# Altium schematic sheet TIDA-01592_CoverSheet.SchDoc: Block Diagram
size 431 x 279 mm; Date: Not shown in title block; ApprovedBy: Not shown in title block; CheckedBy: Not shown in title block; Author: Not shown in title block; CompanyName: Not shown in title block; DrawnBy: Abhishek Vishwa; Engineer: Abhishek Vishwa; Organization: Not shown in title block; Address1: Not shown in title block; Address2: Not shown in title block; Address3: Not shown in title block; Address4: Not shown in title block; DocumentNumber: 1; Revision: Use project parameter SCH_Rev; SheetNumber: 1; SheetTotal: 5; PageSetup: Record=PageOptions¦CenterHorizontal=True¦CenterVertical=True¦PrintScale=1.00¦XCorrection=1.00¦YCorrection=1.00¦PrintKind=0¦BorderSize=5000000¦LeftOffset=0¦BottomOffset=0¦Orientation=2¦PaperLength=1000¦PaperWidth=1000¦Scale=100¦PaperSource=15¦PrintQuality=600¦MediaType=1¦DitherType=10¦PaperKind=Letter¦PrintScaleMode=1
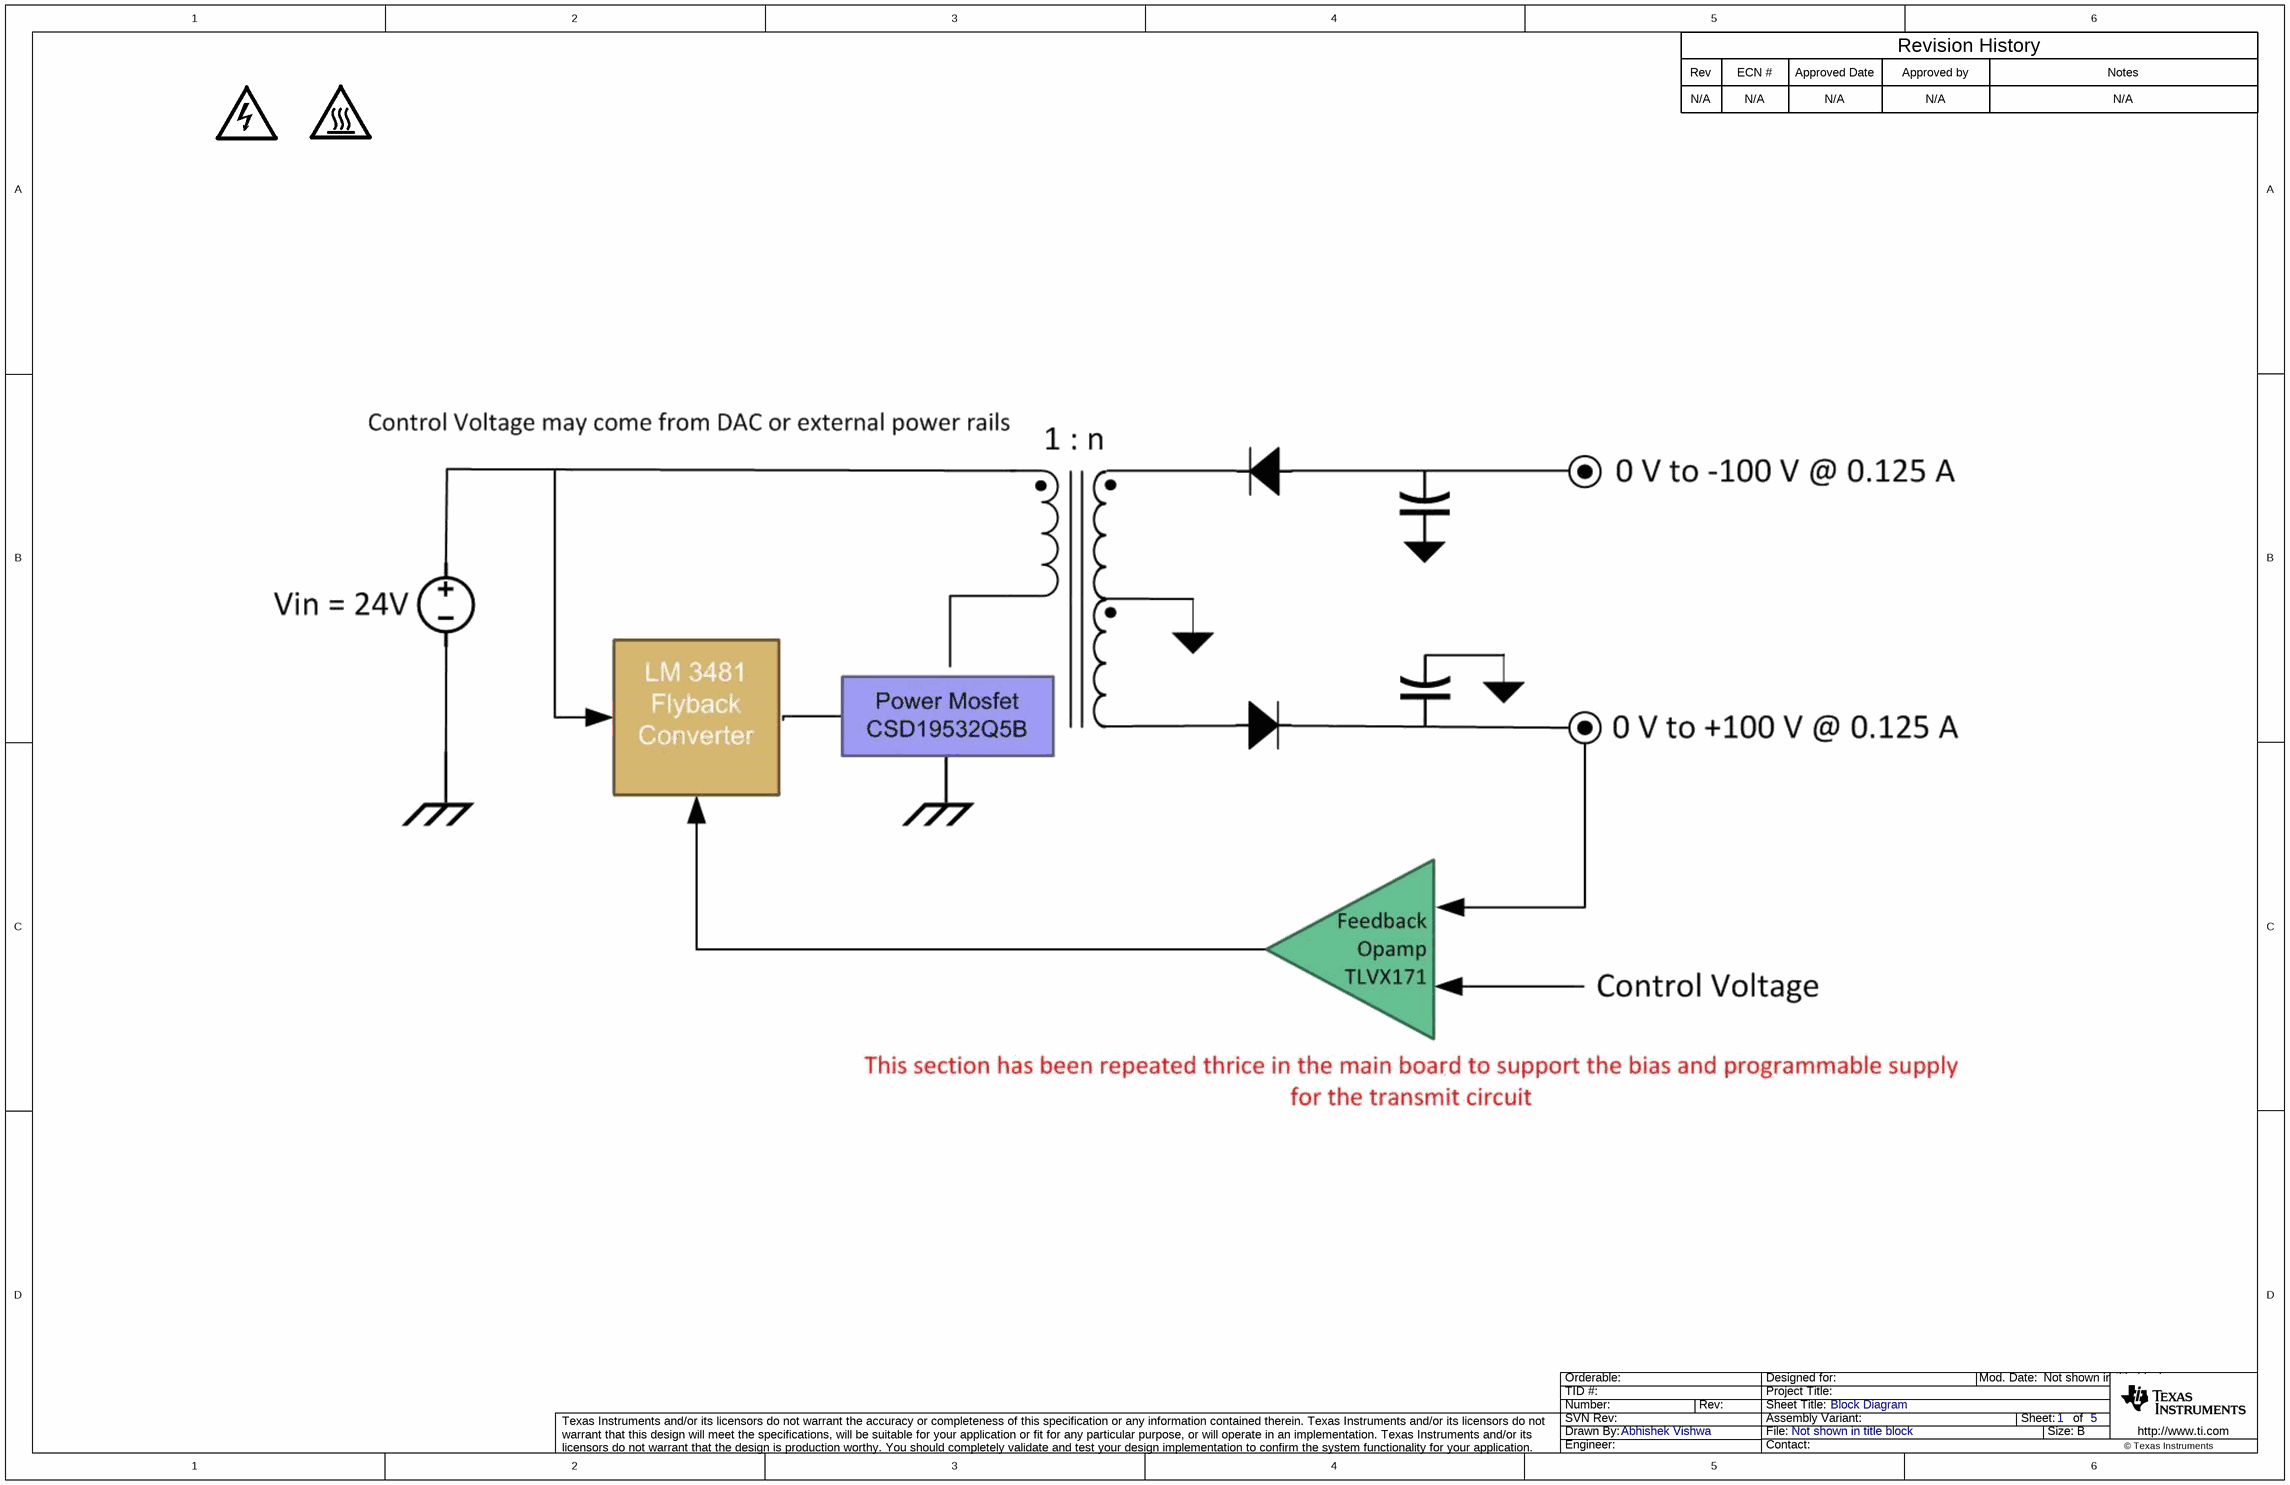
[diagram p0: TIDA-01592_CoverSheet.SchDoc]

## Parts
LOGO2  CAUTION HOT SURFACE  [IEC_HotSurface_Small]  (value not drawn)  (graphical)
LOGO8  DANGER HIGH VOLTAGE  [IEC_HighVoltage_Small]  (value not drawn)  (graphical)

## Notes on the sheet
- Rev
- N/A
- ECN #
- Approved Date
- Approved by
- Revision History
- Notes

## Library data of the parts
LOGO2 = IEC_HotSurface: IEC 61010-1 Hot Surface Warning; SymbolCreator: a0412235
LOGO8 = IEC_HighVoltage: IEC 61010-1 High Voltage Warning; SymbolCreator: a0412235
